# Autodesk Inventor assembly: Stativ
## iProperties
Created: 2007-05
Part Number: Stativ
Document SubType Name: Assembly
Designer: kurs1
Manufacturer: Standard
Standards Organization: Custom
Author: kurs1
